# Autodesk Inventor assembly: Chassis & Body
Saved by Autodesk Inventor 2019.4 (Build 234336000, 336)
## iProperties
Created: 2020-04
Part Number: Chassis & Body
Document SubType Name: Assembly
Designer: Administrator
Title: Chassis & Body v2
Author: Administrator
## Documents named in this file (2)
- c:\worker\convert-fusion-r03\tmp\job-1\8\output\files\d342e430-10cf-4fa0-a064-3c3295007a1f\04208be0-112e-457c-9232-025dcaabcc99.iam
- c:\worker\convert-fusion-r03\tmp\job-1\8\output\files\d342e430-10cf-4fa0-a064-3c3295007a1f\Chassis & Body Work.iam
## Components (1 placed, 1 different names)
1. Chassis & Body Work:1 [sub-assembly]
